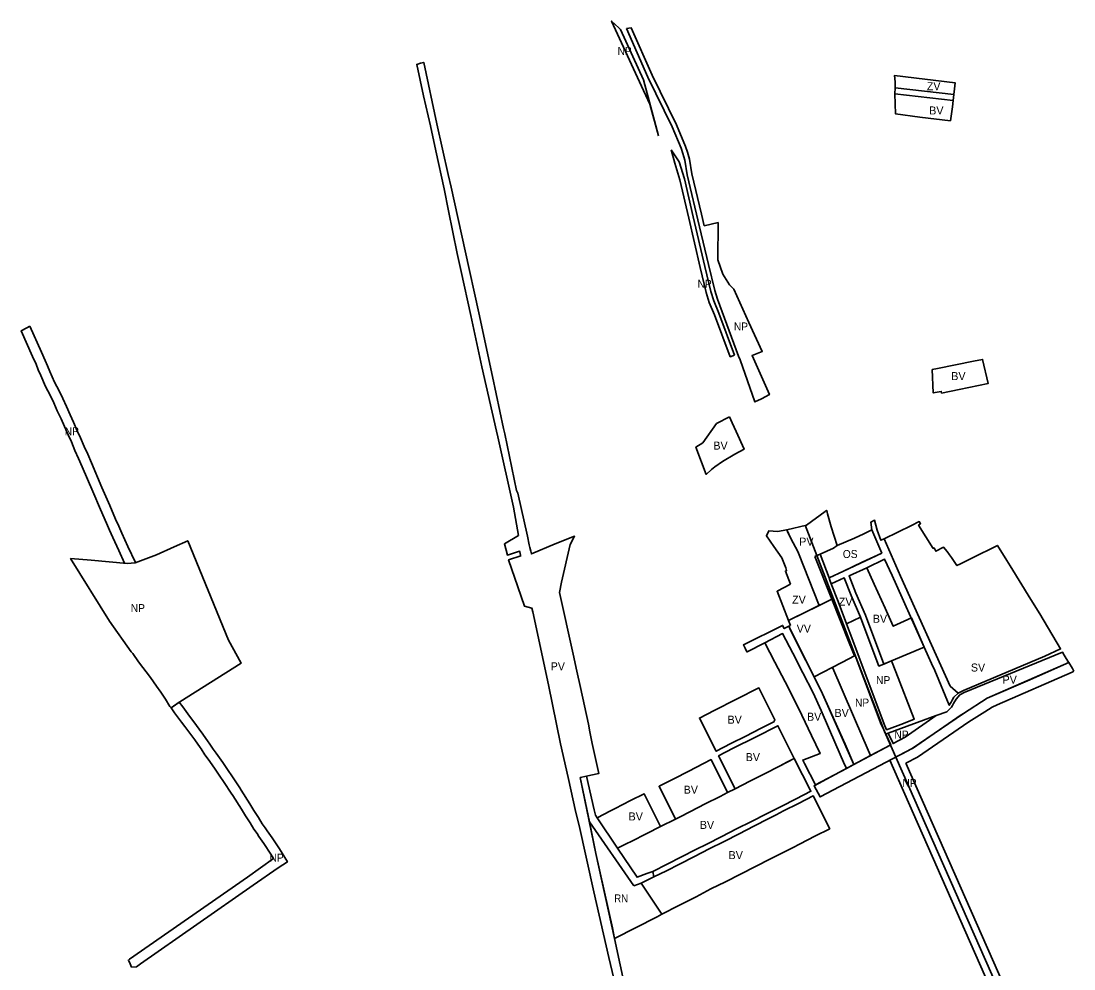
# Model space of a CAD drawing. Extents: x -650276 to -642489, y -1074311 to -1066658.
# Drawn here: x -649558 to -647981, y -1068079 to -1066658 of the extents above; entities that cross this region are included whole.
import ezdxf

# ---------------------------------------------------------------- set-up
doc = ezdxf.new("R2010")
doc.units = 0
doc.header["$LTSCALE"] = 4.8
for name, color, linetype, lineweight in [('15', 7, 'Continuous', 35), ('18', 7, 'Continuous', 35), ('3', 7, 'Continuous', 35), ('40', 7, 'Continuous', 35), ('45', 7, 'Continuous', 35), ('48', 7, 'Continuous', 35), ('54', 7, 'Continuous', 35), ('7', 7, 'Continuous', 35), ('9', 7, 'Continuous', 35)]:
    doc.layers.add(name, color=color, linetype=linetype, lineweight=lineweight)
doc.layers.add('62', color=7, linetype='Continuous')
doc.layers.add('63', color=7, linetype='Continuous')

msp = doc.modelspace()

# ---------------------------------------------------------------- linework, layer by layer
at = {"layer": '15'}
for points in [[(-648662.71, -1068124.76), (-648677.61, -1068061.74), (-648700.16, -1067963.42), (-648722.09, -1067863.84), (-648727.05, -1067844.33), (-648738.7, -1067792.04), (-648749.97, -1067741.49), (-648767.84, -1067652.98), (-648791.68, -1067543.78), (-648792.97, -1067537.86), (-648804.08, -1067534.88), (-648813.94, -1067506.27), (-648827.86, -1067465.86), (-648809.65, -1067459.77), (-648809.97, -1067458.52), (-648811.21, -1067453.52), (-648811.4, -1067452.79), (-648829.54, -1067458.42), (-648834.01, -1067441.81), (-648812.91, -1067429.16), (-648820.39, -1067386.83), (-648844.16, -1067281.37), (-648845.94, -1067272.85), (-648867.82, -1067176.66), (-648884.26, -1067099.63), (-648899.1, -1067033.34), (-648905.06, -1067006.7), (-648917.76, -1066942.65), (-648924.32, -1066909.55), (-648936.7, -1066852.52), (-648944.75, -1066815.41), (-648955.15, -1066770.11), (-648965.39, -1066723.15), (-648959.88, -1066721.59), (-648954.86, -1066720.16), (-648935.19, -1066812.53), (-648918.27, -1066888.41), (-648914.11, -1066907.05), (-648893.02, -1067002.5), (-648872.31, -1067095.5), (-648851.87, -1067191.04), (-648835.29, -1067268.93), (-648833.66, -1067276.77), (-648816.06, -1067361.71), (-648813.81, -1067365.91), (-648799.58, -1067430.4), (-648796.8, -1067443.1), (-648795.88, -1067447.21), (-648794.7, -1067452.46), (-648793.71, -1067456.88), (-648757.97, -1067441.51), (-648728.95, -1067430.33), (-648735.59, -1067442.88), (-648748.53, -1067499.3), (-648751.29, -1067514.57), (-648731.06, -1067607.06), (-648725.8, -1067632.36), (-648720.1, -1067657.12), (-648708.26, -1067712.07), (-648706.08, -1067723.56), (-648702.33, -1067740.84), (-648692.53, -1067785.79), (-648704.614, -1067788.491), (-648710.961, -1067789.906), (-648720.34, -1067792), (-648696.93, -1067905.76), (-648672.31, -1068017.25), (-648668.92, -1068032.96), (-648651.89, -1068111.95)], [(-648710.961, -1067789.906), (-648720.34, -1067792), (-648706.687, -1067858.345), (-648640, -1067954)], [(-648695.27, -1067852.04), (-648697.7, -1067848.43), (-648699.621, -1067840.06), (-648699.593, -1067840.046), (-648710.96, -1067789.91)], [(-648611.61, -1067932.63), (-648620.658, -1067935.93), (-648635.249, -1067941.252), (-648664.41, -1067897.91), (-648695.27, -1067852.04)], [(-648640, -1067954), (-648629.22, -1067950.214), (-648609.91, -1067940.58), (-648611.61, -1067932.63)]]:
    msp.add_lwpolyline(points, dxfattribs=at)
for points in [[(-648161.58, -1066777.41), (-648160.51, -1066768.4), (-648248.43, -1066758.34), (-648248.77, -1066767.43)], [(-648369.01, -1067460.52), (-648361, -1067457.36), (-648341.15, -1067448.14), (-648335.38, -1067444.07), (-648344.41, -1067416.04), (-648349.67, -1067396.88), (-648351.06, -1067391.62), (-648352.16, -1067392.42), (-648353.35, -1067393.29), (-648381.48, -1067413.68), (-648410.92, -1067420.63), (-648409.61, -1067423.44), (-648404.29, -1067434.9), (-648394.92, -1067452.23), (-648393.17, -1067455.88), (-648362.585, -1067534.205), (-648343.41, -1067524.81), (-648369.01, -1067460.52)], [(-648237.81, -1067522.42), (-648204.88, -1067596.54), (-648198.39, -1067610.97), (-648193.8, -1067621), (-648189.03, -1067631.71), (-648167.48, -1067683.45), (-648164.79, -1067678.96), (-648163.11, -1067676.17), (-648160.68, -1067671.55), (-648153.98, -1067665.43), (-648166.173, -1067654.853), (-648240.51, -1067489.9), (-648265.197, -1067434.03), (-648265.197, -1067434.03), (-648270.02, -1067436.37), (-648275.41, -1067421.3), (-648279.24, -1067406.38), (-648285.08, -1067409.24), (-648283.21, -1067420.88), (-648268.67, -1067455.43), (-648297.915, -1067469.319), (-648326.09, -1067482.7), (-648347.51, -1067492.87), (-648346.27, -1067496.14), (-648344.186, -1067501.627), (-648324.735, -1067492.8), (-648314.647, -1067519.171), (-648300.258, -1067551.772), (-648299.23, -1067554.52), (-648272.941, -1067624.811), (-648265.601, -1067621.762), (-648292.991, -1067548.356), (-648307.57, -1067515.44), (-648317.435, -1067489.488), (-648291.172, -1067477.571), (-648264.34, -1067464.83), (-648253.1, -1067489.23)], [(-648359.6, -1067691.58), (-648348.55, -1067716.71), (-648337.32, -1067742.59), (-648326, -1067769), (-648321.623, -1067778.399), (-648310.511, -1067772.476), (-648323.178, -1067741.953), (-648359.213, -1067661.956), (-648405.054, -1067571.837), (-648408.002, -1067565.219), (-648414.73, -1067568.8), (-648417.19, -1067564.02), (-648475.78, -1067593.11), (-648473.34, -1067598.06), (-648470.57, -1067603.69), (-648470.47, -1067603.64), (-648443.83, -1067589.92), (-648417.12, -1067576.17), (-648402.02, -1067605.49), (-648386.91, -1067634.83), (-648371.34, -1067665.08)], [(-647988.235, -1067619.912), (-647995.04, -1067608.56), (-647997.68, -1067604.11), (-648144.83, -1067664.48), (-648151.6, -1067668.12), (-648157.2, -1067674.32), (-648161, -1067680.96), (-648162.69, -1067684), (-648164.09, -1067686.51), (-648171.21, -1067693.37), (-648187.139, -1067699.179), (-648233.264, -1067731.288), (-648251.711, -1067741.124), (-648258.96, -1067725.37), (-648262.632, -1067726.711), (-648255.016, -1067742.886), (-648319.983, -1067777.526), (-648370.113, -1067804.22), (-648360.993, -1067821.027), (-648222.872, -1067748.412), (-648146.127, -1067695.8), (-648110.36, -1067673.133), (-647988.052, -1067619.624)]]:
    msp.add_lwpolyline(points, close=True, dxfattribs=at)
at = {"layer": '18'}
msp.add_lwpolyline([(-648153.98, -1067665.43), (-648149.933, -1067663.646), (-648146.21, -1067661.3), (-648023.96, -1067610.13), (-648000.63, -1067599.14), (-648031.77, -1067546.6), (-648045.04, -1067525.15), (-648076.32, -1067474.6), (-648081.31, -1067466.54), (-648095.28, -1067444.06), (-648133.56, -1067463.2), (-648150.46, -1067471.66), (-648155.85, -1067474.35), (-648164.24, -1067462.15), (-648166.97, -1067458.18), (-648170.38, -1067453.23), (-648175.94, -1067446.89), (-648187.44, -1067452.8), (-648190.23, -1067447.83), (-648191.46, -1067448.59), (-648213.34, -1067413.46), (-648210.48, -1067411.68), (-648211.08, -1067410.6), (-648212.32, -1067408.39), (-648224.19, -1067414.14), (-648265.197, -1067434.03), (-648240.51, -1067489.9), (-648240.51, -1067489.9), (-648166.173, -1067654.853)], close=True, dxfattribs=at)
at = {"layer": '3'}
for points in [[(-648165.33, -1066807.74), (-648162.8, -1066786.8), (-648161.58, -1066777.41), (-648248.77, -1066767.43), (-648247.78, -1066797.53), (-648211.58, -1066802.18)], [(-648185.185, -1067178.687), (-648193.02, -1067180.66), (-648191.44, -1067215.62), (-648179.42, -1067213.37), (-648179, -1067215.71), (-648152.5, -1067210.23), (-648109.1, -1067201.21), (-648117.562, -1067165.197), (-648131.01, -1067167.84)], [(-648496.55, -1067251.53), (-648516.47, -1067261.54), (-648536.84, -1067290.29), (-648547.17, -1067296.68), (-648531.51, -1067337.57), (-648523.55, -1067330.33), (-648518.55, -1067326.3), (-648507.25, -1067318.35), (-648488.66, -1067307.11), (-648474.69, -1067299.66), (-648486.79, -1067273.26), (-648492.62, -1067260.53)], [(-648263.7, -1067537.93), (-648279.86, -1067502.11), (-648291.17, -1067477.57), (-648317.435, -1067489.488), (-648307.57, -1067515.44), (-648292.991, -1067548.356), (-648265.601, -1067621.762), (-648254.04, -1067616.96), (-648254.04, -1067616.96), (-648204.88, -1067596.54), (-648224.16, -1067552.55), (-648251.33, -1067565.28)], [(-648397.98, -1067678.79), (-648388.526, -1067698.603), (-648373.99, -1067728.95), (-648361.08, -1067755.88), (-648387.04, -1067765.67), (-648384.25, -1067771.07), (-648367.811, -1067802.994), (-648321.623, -1067778.399), (-648326, -1067769), (-648337.32, -1067742.59), (-648348.55, -1067716.71), (-648359.6, -1067691.58), (-648371.34, -1067665.08), (-648386.91, -1067634.83), (-648402.02, -1067605.49), (-648417.12, -1067576.17), (-648443.83, -1067589.92), (-648428.7, -1067619.24), (-648413.57, -1067648.57)], [(-648342.697, -1067626.806), (-648369.949, -1067640.851), (-648359.213, -1067661.956), (-648310.511, -1067772.476), (-648285.254, -1067759.008), (-648296.891, -1067732.172), (-648342.023, -1067628.096)], [(-648519.63, -1067691.58), (-648541.86, -1067702.86), (-648516.73, -1067752.57), (-648494.84, -1067741.06), (-648472.5, -1067729.76), (-648450.23, -1067718.32), (-648430.17, -1067708.33), (-648428.67, -1067705.52), (-648452.72, -1067657.62)], [(-648491.14, -1067748.02), (-648513.23, -1067759.38), (-648488.49, -1067808.76), (-648466.36, -1067797.5), (-648455.32, -1067791.85), (-648444.28, -1067786.19), (-648421.84, -1067774.66), (-648410.78, -1067768.98), (-648399.64, -1067763.26), (-648424.14, -1067714.34), (-648435.34, -1067720.01), (-648446.58, -1067725.71), (-648468.97, -1067736.91), (-648480.06, -1067742.47)], [(-648577.78, -1067854.07), (-648571.69, -1067851.06), (-648555.32, -1067842.99), (-648532.98, -1067831.54), (-648510.82, -1067820.19), (-648499.7, -1067814.37), (-648524.44, -1067765.11), (-648535.61, -1067770.85), (-648557.84, -1067782.26), (-648580.14, -1067793.61), (-648602.3, -1067804.83)], [(-648644.095, -1067887.6), (-648620.51, -1067875.63), (-648600.14, -1067865.29), (-648624.76, -1067816.11), (-648645.11, -1067826.48), (-648668.085, -1067838.186), (-648675.26, -1067841.84), (-648695.27, -1067852.04), (-648664.41, -1067897.91), (-648650.68, -1067890.94)]]:
    msp.add_lwpolyline(points, close=True, dxfattribs=at)
for points in [[(-648611.61, -1067932.63), (-648611.61, -1067932.63), (-648547.09, -1067899.87), (-648530.81, -1067891.61), (-648508.22, -1067880.38), (-648486.09, -1067868.98), (-648463.91, -1067857.74), (-648441.47, -1067846.37), (-648419.44, -1067835.3), (-648397.04, -1067823.85), (-648374.84, -1067812.43), (-648399.64, -1067763.26), (-648421.84, -1067774.66)], [(-648421.84, -1067774.66), (-648444.28, -1067786.19), (-648455.32, -1067791.85), (-648466.36, -1067797.5), (-648488.49, -1067808.76)], [(-648488.49, -1067808.76), (-648499.7, -1067814.37), (-648510.82, -1067820.19), (-648532.98, -1067831.54), (-648555.32, -1067842.99), (-648571.69, -1067851.06)], [(-648572.5, -1067983.59), (-648546.76, -1067970.44), (-648524.72, -1067958.93), (-648502.59, -1067948), (-648480.12, -1067936.55), (-648457.87, -1067925.4), (-648435.55, -1067913.84), (-648413.41, -1067902.53), (-648402.29, -1067897.02), (-648391.08, -1067891.24), (-648368.78, -1067879.75), (-648346.57, -1067868.56), (-648371.27, -1067819.47), (-648393.35, -1067830.81), (-648415.69, -1067841.98), (-648426.65, -1067847.64), (-648437.89, -1067853.4), (-648460.33, -1067864.88), (-648482.5, -1067876.22), (-648504.92, -1067887.52), (-648527.33, -1067898.74), (-648549.44, -1067910.07), (-648571.88, -1067921.71), (-648591.04, -1067931.62), (-648609.91, -1067940.58)], [(-648571.69, -1067851.06), (-648577.78, -1067854.07), (-648600.14, -1067865.29)], [(-648600.14, -1067865.29), (-648620.51, -1067875.63), (-648644.095, -1067887.6)], [(-648644.095, -1067887.6), (-648650.68, -1067890.94), (-648664.41, -1067897.91), (-648635.249, -1067941.252), (-648620.658, -1067935.93), (-648611.61, -1067932.63)], [(-648609.91, -1067940.58), (-648629.22, -1067950.214), (-648597.93, -1067996.72), (-648572.5, -1067983.59)]]:
    msp.add_lwpolyline(points, dxfattribs=at)
at = {"layer": '40'}
for points in [[(-648160.51, -1066768.4), (-648159.66, -1066759.8), (-648158.49, -1066750.93), (-648249.44, -1066739.8), (-648248.34, -1066749.33), (-648248.43, -1066758.34)], [(-648405.27, -1067502.27), (-648425.5, -1067512.73), (-648408.26, -1067556.58), (-648362.585, -1067534.205), (-648393.17, -1067455.88), (-648394.92, -1067452.23), (-648404.29, -1067434.9), (-648410.92, -1067420.63), (-648425, -1067423.05), (-648437.75, -1067421.99), (-648441.48, -1067429.63), (-648430.4, -1067445.51), (-648418.3, -1067462.86), (-648412.46, -1067477.42), (-648411.25, -1067481.73), (-648412.89, -1067482.55)], [(-648324.735, -1067492.8), (-648344.186, -1067501.627), (-648334.09, -1067528.2), (-648321.36, -1067561.69), (-648300.258, -1067551.772), (-648314.647, -1067519.171)]]:
    msp.add_lwpolyline(points, close=True, dxfattribs=at)
for points in [[(-648314.647, -1067519.171), (-648324.735, -1067492.8), (-648344.186, -1067501.627)], [(-648344.186, -1067501.627), (-648334.09, -1067528.2), (-648321.36, -1067561.69)], [(-648321.36, -1067561.69), (-648300.258, -1067551.772), (-648314.647, -1067519.171)]]:
    msp.add_lwpolyline(points, dxfattribs=at)
at = {"layer": '45'}
msp.add_lwpolyline([(-648405.41, -1067563.84), (-648408.002, -1067565.219), (-648369.949, -1067640.851), (-648342.697, -1067626.806), (-648328.54, -1067619.51), (-648309.522, -1067609.713), (-648317.43, -1067590), (-648343.41, -1067524.81), (-648408.26, -1067556.58)], close=True, dxfattribs=at)
at = {"layer": '48'}
for points in [[(-648602.97, -1066830.11), (-648616.86, -1066779.79), (-648625.44, -1066746.45), (-648659.95, -1066670.89), (-648662.46, -1066668.53), (-648673.407, -1066658.275), (-648631.791, -1066749.394)], [(-648534.701, -1066965.077), (-648538.812, -1066947.891), (-648553.323, -1066887.238), (-648556.637, -1066865.397), (-648559.94, -1066854.66), (-648562.542, -1066846.219), (-648576.145, -1066813.802), (-648612.763, -1066739.165), (-648643.925, -1066668.483), (-648651.042, -1066669.551), (-648651.1, -1066669.56)], [(-648651.1, -1066669.56), (-648619.11, -1066742.12), (-648582.52, -1066816.7)], [(-648631.791, -1066749.394), (-648616.104, -1066782.727), (-648602.97, -1066830.11)], [(-648582.52, -1066816.7), (-648569.13, -1066848.61), (-648566.63, -1066856.72), (-648563.48, -1066866.96), (-648560.2, -1066888.58), (-648541.521, -1066966.657), (-648541.52, -1066966.657)], [(-648571.96, -1066869.37), (-648577.99, -1066860.17), (-648583.94, -1066851.11)], [(-648583.94, -1066851.11), (-648578.702, -1066871.259), (-648571.167, -1066896.326), (-648557.816, -1066953.444)], [(-648489.1, -1067158.84), (-648512.95, -1067095.97), (-648520.4, -1067077.42), (-648524.93, -1067063.35), (-648533.66, -1067026), (-648551, -1066951.85), (-648564.4, -1066894.52), (-648571.96, -1066869.37)], [(-648557.816, -1066953.444), (-648540.476, -1067027.594), (-648531.681, -1067065.222)], [(-648541.52, -1066966.657), (-648528.01, -1067023.13), (-648518.72, -1067061.99), (-648514.86, -1067074.83), (-648507.88, -1067093.9), (-648483.31, -1067160.63), (-648480.57, -1067166.13), (-648458.73, -1067229.1), (-648449.03, -1067224.14), (-648437.02, -1067217.99), (-648462.97, -1067159.24), (-648447.66, -1067153.25), (-648467.56, -1067110.02), (-648490.23, -1067060.06), (-648496.87, -1067053.5), (-648506.78, -1067037.81), (-648514.38, -1067016.2), (-648513.842, -1066960.243), (-648534.701, -1066965.077)], [(-648531.681, -1067065.222), (-648526.988, -1067079.8), (-648519.471, -1067098.516), (-648495.644, -1067161.326), (-648489.1, -1067158.84)], [(-648254.04, -1067616.96), (-648272.941, -1067624.811), (-648300.258, -1067551.772), (-648321.36, -1067561.69)], [(-648321.36, -1067561.69), (-648311.95, -1067586.45), (-648265.08, -1067712.06)], [(-648265.08, -1067712.06), (-648261.25, -1067720.39), (-648235.78, -1067710.79), (-648219.86, -1067704.42), (-648247.53, -1067633.53), (-648254.04, -1067616.96)], [(-647980.561, -1067632.719), (-647982.95, -1067628.73), (-647988.334, -1067619.747), (-648046.773, -1067645.314)], [(-648095.475, -1067682.994), (-647983.06, -1067633.813), (-647980.561, -1067632.719)], [(-648046.773, -1067645.314), (-648110.36, -1067673.133), (-648146.127, -1067695.8), (-648146.146, -1067695.813), (-648149.529, -1067698.132), (-648222.53, -1067748.178)], [(-648232.676, -1067770.513), (-648215.115, -1067761.28), (-648137.869, -1067708.325), (-648114.323, -1067693.403), (-648103.298, -1067686.416), (-648095.475, -1067682.994)], [(-648222.53, -1067748.178), (-648222.872, -1067748.412), (-648238.748, -1067756.759)], [(-648238.748, -1067756.759), (-648256.499, -1067766.091), (-648079.002, -1068168.139)], [(-648079.002, -1068168.139), (-648061.329, -1068158.649), (-648232.676, -1067770.513)]]:
    msp.add_lwpolyline(points, dxfattribs=at)
for points in [[(-649545.203, -1067115.647), (-649549.7, -1067118.05), (-649558.469, -1067122.73), (-649541.537, -1067160.722), (-649536.075, -1067172.622), (-649532.831, -1067180.855), (-649529.013, -1067189.389), (-649521.663, -1067206.124), (-649514.869, -1067218.957), (-649509.44, -1067230.141), (-649504.224, -1067242.225), (-649498.572, -1067254.427), (-649493.526, -1067265.611), (-649487.812, -1067278.312), (-649482.963, -1067288.934), (-649477.677, -1067301.655), (-649472.327, -1067313.644), (-649466.703, -1067326.24), (-649451.059, -1067363.074), (-649439.265, -1067390.397), (-649430.531, -1067410.689), (-649425.804, -1067421.21), (-649421.071, -1067431.944), (-649411.913, -1067451.746), (-649403.34, -1067470.579), (-649399.39, -1067470.93), (-649387.4, -1067469.98), (-649387.17, -1067469.894), (-649398.28, -1067445.49), (-649407.4, -1067425.77), (-649412.1, -1067415.11), (-649416.8, -1067404.65), (-649425.49, -1067384.46), (-649437.27, -1067357.17), (-649452.95, -1067320.25), (-649458.63, -1067307.53), (-649463.9, -1067295.72), (-649469.21, -1067282.94), (-649474.15, -1067272.12), (-649479.85, -1067259.45), (-649484.93, -1067248.19), (-649490.53, -1067236.1), (-649495.8, -1067223.89), (-649501.49, -1067212.17), (-649508.15, -1067199.59), (-649515.3, -1067183.31), (-649519, -1067175.04), (-649522.27, -1067166.74), (-649527.87, -1067154.54)], [(-649333.74, -1067687.4), (-649335.26, -1067685.21), (-649341.81, -1067674.33), (-649349.12, -1067663.84), (-649355.46, -1067654.85), (-649364.69, -1067641.98), (-649382.53, -1067618.33), (-649391.04, -1067606.27), (-649393.23, -1067603.28), (-649425.69, -1067557.7), (-649484.28, -1067463.88), (-649453.39, -1067466.13), (-649399.39, -1067470.93), (-649387.4, -1067469.98), (-649355.44, -1067457.94), (-649329.068, -1067446.175), (-649308.75, -1067437.11), (-649247.518, -1067586.255), (-649228.52, -1067620.294), (-649320.47, -1067678.44)], [(-648342.023, -1067628.096), (-648296.891, -1067732.172), (-648285.254, -1067759.008), (-648255.016, -1067742.886), (-648265.614, -1067720.378), (-648269.27, -1067712.6), (-648308.43, -1067609.15), (-648328.54, -1067619.51), (-648342.697, -1067626.806)], [(-649321.3, -1067679), (-649333.74, -1067687.4), (-649328.34, -1067694.79), (-649317.99, -1067708.85), (-649312.91, -1067715.45), (-649298.02, -1067735.58), (-649290.15, -1067746.92), (-649288.63, -1067748.97), (-649282.85, -1067757.79), (-649278.14, -1067764.31), (-649268.46, -1067777.97), (-649261.48, -1067788.47), (-649253.98, -1067799.2), (-649243.37, -1067815.17), (-649241.28, -1067818.7), (-649228.27, -1067839.26), (-649222.11, -1067849.12), (-649215.32, -1067859.99), (-649209.39, -1067869.34), (-649204.87, -1067875.85), (-649202.02, -1067880.07), (-649194.77, -1067890.67), (-649184, -1067906.88), (-649179.96, -1067913.35), (-649219.088, -1067940.964), (-649395.729, -1068064.23), (-649397.466, -1068065.442), (-649394.83, -1068071.05), (-649392.88, -1068075.9), (-649385.41, -1068075.32), (-649379.295, -1068071.053), (-649210.54, -1067953.29), (-649172.99, -1067927.41), (-649159.179, -1067918.309), (-649171.389, -1067898.756), (-649182.332, -1067882.285), (-649189.614, -1067871.638), (-649192.493, -1067867.375), (-649196.89, -1067861.042), (-649202.625, -1067852), (-649209.388, -1067841.173), (-649215.571, -1067831.276), (-649228.486, -1067810.867), (-649230.661, -1067807.193), (-649241.584, -1067790.752), (-649249.085, -1067780.02), (-649256.092, -1067769.48), (-649265.941, -1067755.582), (-649270.491, -1067749.283), (-649276.322, -1067740.385), (-649277.961, -1067738.175), (-649285.826, -1067726.842), (-649300.936, -1067706.414), (-649306.005, -1067699.828), (-649316.244, -1067685.919)], [(-648258.96, -1067725.37), (-648251.711, -1067741.124), (-648233.264, -1067731.288), (-648187.139, -1067699.179)]]:
    msp.add_lwpolyline(points, close=True, dxfattribs=at)
at = {"layer": '54'}
msp.add_lwpolyline([(-648383.36, -1067413.938), (-648264.607, -1067722.965), (-648014.937, -1068288.491)], dxfattribs=at)
at = {"layer": '7'}
msp.add_lwpolyline([(-648640, -1067954), (-648706.687, -1067858.345), (-648696.93, -1067905.76), (-648668.92, -1068032.96), (-648605.323, -1068000.463), (-648597.93, -1067996.72), (-648629.22, -1067950.214)], close=True, dxfattribs=at)
at = {"layer": '9'}
msp.add_lwpolyline([(-648268.67, -1067455.43), (-648283.21, -1067420.88), (-648295.66, -1067426.76), (-648309.57, -1067433.34), (-648335.38, -1067444.07), (-648341.15, -1067448.14), (-648361, -1067457.36), (-648347.51, -1067492.87), (-648326.09, -1067482.7)], close=True, dxfattribs=at)

# ---------------------------------------------------------------- texts
at = {"layer": '62'}
for s, width, p in [('NP', 0.95, (-648664.583, -1066709.041)), ('NP', 0.95, (-648544.583, -1067058.041)), ('NP', 0.95, (-648490.15, -1067121.972)), ('NP', 0.95, (-649492.985, -1067278.967)), ('NP', 0.95, (-649393.985, -1067543.967)), ('NP', 0.95, (-648277.019, -1067651.94)), ('NP', 0.95, (-648308.631, -1067685.579)), ('NP', 0.95, (-648237.583, -1067806.041)), ('NP', 0.95, (-649185.985, -1067917.967)), ('RN', 0.9, (-648669.473, -1067979.058))]:
    msp.add_text(s, height=12, dxfattribs=dict(at, width=width)).set_placement(p)
for s, p in [('ZV', (-648201.026, -1066761.906)), ('BV', (-648197.475, -1066798.284)), ('BV', (-648164.386, -1067196.331)), ('BV', (-648520.956, -1067300.498)), ('PV', (-648392.213, -1067444.317)), ('ZV', (-648402.918, -1067531.307)), ('ZV', (-648332.918, -1067534.307)), ('VV', (-648396.075, -1067574.614)), ('PV', (-648764.767, -1067631.209)), ('SV', (-648135.028, -1067633.035)), ('PV', (-648087.517, -1067651.275)), ('BV', (-648339.301, -1067701.063)), ('BV', (-648499.724, -1067711.153)), ('BV', (-648380.551, -1067706.775)), ('BV', (-648472.48, -1067767.243)), ('BV', (-648565.429, -1067816.121)), ('BV', (-648647.961, -1067856.185)), ('BV', (-648541.281, -1067868.87)), ('BV', (-648498.112, -1067914.191))]:
    msp.add_text(s, height=12, dxfattribs=at).set_placement(p)
at = {"layer": '63', "width": 0.95}
for s, p in [('OS', (-648326.942, -1067462.923)), ('NP', (-648249.631, -1067733.579))]:
    msp.add_text(s, height=12, dxfattribs=at).set_placement(p)
at = {"layer": '63'}
msp.add_text('BV', height=12, dxfattribs=at).set_placement((-648281.942, -1067559.923))

doc.saveas('drawing.dxf')
